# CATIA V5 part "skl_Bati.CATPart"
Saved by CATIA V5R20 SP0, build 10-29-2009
Part number: skl_Bati
Publications: "Axe_pivot_BatiF_F", "Point_O", "droite_Bati"
Bounding box of the stored display mesh (mm): x -15 to 20, y -29.269 to 29.269, z -44.292 to 5.991
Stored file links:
  D:\Dropbox\IAO_2012\IAO_2012_742_prousseau\skl_Bati.CATPart
  D:\Dropbox\IAO_2012\IAO_2012_742_prousseau\skl_IAO.CATProduct
  D:\Dropbox\IAO_2012\IAO_2012_742_prousseau\skl_barre_EF.CATPart
  D:\Dropbox\IAO_2012\IAO_2012_742_prousseau\skl_general.CATPart
  D:\Dropbox\IAO_2012\IAO_2012_742_prousseau\skl_barre_FC.CATPart
  D:\Dropbox\IAO_2012\IAO_2012_742_prousseau\skl_barre_AB.CATPart
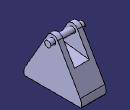
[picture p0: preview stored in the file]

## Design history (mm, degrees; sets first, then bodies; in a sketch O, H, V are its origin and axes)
Set1
  Point1 "Point_F": linked copy from another document
  Point2 "Point_O": linked copy from another document
  Point3 "Point_F": linked copy from another document
  Plane1: linked copy from another document
  DatumCurve1: linked copy from another document
  DatumCurve2: linked copy from another document
  Plane2: linked copy from another document
  Plane3: linked copy from another document
  DatumCurve3: linked copy from another document
Set2
  Line1 "droite_Bati": type PtPt, FirstPoint Point1, SecondPoint Point2
  Line2 "Axe_pivot_BatiF_F": type Normal, RefPoint Point1, RefSkin Plane4, Start -20, End 20
  Plane4 "Plan_Ref": stored without definition
Body1 (main body)
  Sketch1 on yz-plane, origin (0, 0, 0), H (0, 1, 0), V (0, 0, 1)
    arc A1 centre (0, 0) radius 6 from (5.1962, 3) to (-5.1962, 3) ccw
    point P1 (0, 0)
    reference projected point E1 (0, 0) from Point3
    line L1 (5.1962, 3) -> (32.5, -44.2917)
    line L2 (-5.1962, 3) -> (-32.5, -44.2917)
    line L3 (-32.5, -44.2917) -> (32.5, -44.2917)
    radius A1 = 6
    angle L2 L3 = 60
    angle L1 L3 = 60
    length L3 = 65
    coincidence: P1 E1
    horizontal: L3 H
    tangency: L1 A1, L2 A1
  Pad1: profile Sketch1, direction (1, 0, 0), length 15, opposite side length 10
  Sketch2 on Plane3, origin (0, 1.2073, 9.5564), H (-1, 0, 0), V (0, -0.9921, 0.1253)
    line L1 (-10, 20) -> (5, 20)
    line L2 (5, 20) -> (5, -20)
    line L3 (5, -20) -> (-10, -20)
    line L4 (-10, -20) -> (-10, 20)
    reference projected line E1 (-10, -21.1866) -> (-10, 2.1049) from edge of DatumCurve3
    reference projected line E2 (5, -94.0108) -> (5, -3.3059) from DatumCurve2
    reference projected point E3 (0, 0) from Point1
    length L4 = 40
    horizontal: L1 H, L3 H
    vertical: L2 V, L4 V
    coincidence: L4 E1, L2 E2
    equidistance: L1 L3 E3
  Pocket1: profile Sketch2, direction (0, -0.1253, -0.9921), length 25
  Chamfer1: length 5, angle 45, on edge [face of Pad1 from Sketch1.L3 | face of Pad1 from Sketch1.L2]
  Chamfer2: length 5, angle 45, on edge [face of Pad1 from Sketch1.L1 | face of Pad1 from Sketch1.L3]
  Fillet1: radius 10, on edge [face of Chamfer1 | face of Pad1 from Sketch1.L2]
  Fillet2: radius 10, on edge [face of Pad1 from Sketch1.L1 | face of Chamfer2]
  Sketch3 on end face of Pad1, origin (15, 0, 0), H (0, 1, 0), V (0, 0, 1)
    point P1 (0, 0)
    reference projected point E1 (0, 0) from vertex of Line2
    coincidence: E1 P1
  Hole1: placed by Sketch3, at (15, 0, 0) direction (-1, 0, 0), diameter 6, up to start face of Pad1
Body2
  Sketch4 on end face of Pad1, origin (15, 0, 0), H (0, 1, 0), V (0, 0, 1)
    circle A1 centre (0, 0) radius 3
    point P1 (0, 0)
    reference projected point E1 (0, 0) from Point3
    radius A1 = 3
    coincidence: P1 E1
  Pad2: profile Sketch4, direction (-1, 0, 0), length 30, opposite side length 5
